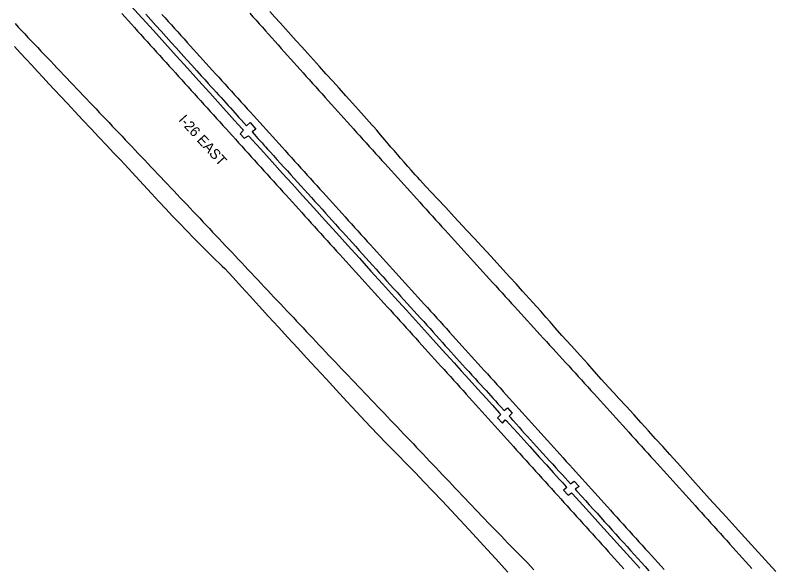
# Model space of a CAD drawing. Extents: x 1948091 to 1975253, y 787267 to 823306.
# Drawn here: x 1958564 to 1958967.8, y 810575.6 to 810868.4 of the extents above; entities that cross this region are included whole.
import ezdxf

# ---------------------------------------------------------------- set-up
doc = ezdxf.new("R2010")
doc.units = 0
for name, color, linetype in [('RD_EX_Pavement_Markings', 7, 'Continuous'), ('RD_EX_Road', 7, 'Continuous'), ('RD_TX_RoadID', 7, 'Continuous')]:
    doc.layers.add(name, color=color, linetype=linetype)

msp = doc.modelspace()

# ---------------------------------------------------------------- linework, layer by layer
at = {"layer": 'RD_EX_Pavement_Markings'}
for points in [[(1958620.62, 810869.28), (1958622.29, 810867.42), (1958623.97, 810865.57), (1958625.64, 810863.71), (1958627.31, 810861.85), (1958628.99, 810860), (1958630.66, 810858.14), (1958632.33, 810856.29), (1958634.01, 810854.43), (1958635.68, 810852.58), (1958637.35, 810850.72), (1958639.03, 810848.87), (1958640.7, 810847.01), (1958642.38, 810845.16), (1958644.06, 810843.31), (1958645.73, 810841.46), (1958647.41, 810839.6), (1958649.09, 810837.75), (1958650.76, 810835.9), (1958652.44, 810834.04), (1958654.12, 810832.19), (1958655.79, 810830.34), (1958657.47, 810828.48), (1958659.15, 810826.63), (1958660.82, 810824.78), (1958662.5, 810822.92), (1958664.18, 810821.07), (1958665.85, 810819.22), (1958667.53, 810817.36), (1958669.21, 810815.51), (1958670.88, 810813.66), (1958672.56, 810811.8), (1958674.24, 810809.95), (1958675.91, 810808.1), (1958677.59, 810806.25), (1958679.27, 810804.39), (1958680.94, 810802.54), (1958682.62, 810800.69), (1958684.3, 810798.83), (1958685.97, 810796.98), (1958687.65, 810795.13), (1958689.33, 810793.27), (1958691.01, 810791.42), (1958692.68, 810789.57), (1958694.36, 810787.72), (1958696.04, 810785.86), (1958697.71, 810784.01), (1958699.39, 810782.16), (1958701.07, 810780.3), (1958702.75, 810778.45), (1958704.42, 810776.6), (1958706.1, 810774.74), (1958707.78, 810772.89), (1958709.46, 810771.04), (1958711.13, 810769.19), (1958712.81, 810767.33), (1958714.49, 810765.48), (1958716.17, 810763.63), (1958717.84, 810761.77), (1958719.52, 810759.92), (1958721.2, 810758.07), (1958722.88, 810756.21), (1958724.55, 810754.36), (1958726.23, 810752.51), (1958727.91, 810750.66), (1958729.59, 810748.8), (1958731.26, 810746.95), (1958732.94, 810745.1), (1958734.62, 810743.24), (1958736.3, 810741.39), (1958737.98, 810739.54), (1958739.66, 810737.69), (1958741.34, 810735.84), (1958743.01, 810733.99), (1958744.69, 810732.13), (1958746.37, 810730.28), (1958748.05, 810728.43), (1958749.73, 810726.58), (1958751.41, 810724.73), (1958753.09, 810722.87), (1958754.77, 810721.02), (1958756.45, 810719.17), (1958758.13, 810717.32), (1958759.81, 810715.47), (1958761.49, 810713.62), (1958763.16, 810711.76), (1958764.84, 810709.91), (1958766.52, 810708.06), (1958768.2, 810706.21), (1958769.88, 810704.36), (1958771.56, 810702.5), (1958773.24, 810700.65), (1958774.92, 810698.8), (1958776.6, 810696.95), (1958778.28, 810695.1), (1958779.95, 810693.24), (1958781.63, 810691.39), (1958783.3, 810689.53), (1958784.98, 810687.68), (1958786.65, 810685.82), (1958788.33, 810683.97), (1958790.01, 810682.11), (1958791.68, 810680.26), (1958793.36, 810678.4), (1958795.03, 810676.55), (1958796.71, 810674.69), (1958798.38, 810672.84), (1958800.06, 810670.98), (1958801.74, 810669.13), (1958803.41, 810667.27), (1958805.09, 810665.42), (1958806.76, 810663.56), (1958808.44, 810661.7), (1958810.11, 810659.85), (1958811.79, 810657.99), (1958813.47, 810656.14), (1958815.14, 810654.28), (1958816.82, 810652.43), (1958818.49, 810650.57), (1958820.17, 810648.72), (1958821.84, 810646.86), (1958823.52, 810645.01), (1958825.2, 810643.15), (1958826.87, 810641.3), (1958828.55, 810639.44), (1958830.22, 810637.59), (1958831.9, 810635.73), (1958833.57, 810633.87), (1958835.25, 810632.02), (1958836.92, 810630.16), (1958838.6, 810628.31), (1958840.27, 810626.45), (1958841.95, 810624.59), (1958843.62, 810622.74), (1958845.3, 810620.88), (1958846.97, 810619.03), (1958848.65, 810617.17), (1958850.32, 810615.31), (1958852, 810613.46), (1958853.67, 810611.6), (1958855.35, 810609.75), (1958857.02, 810607.89), (1958858.7, 810606.03), (1958860.37, 810604.18), (1958862.05, 810602.32), (1958863.72, 810600.47), (1958865.4, 810598.61), (1958867.07, 810596.76), (1958868.75, 810594.9), (1958870.42, 810593.04), (1958872.1, 810591.19), (1958873.77, 810589.33), (1958875.45, 810587.48), (1958877.13, 810585.63), (1958878.81, 810583.77), (1958880.48, 810581.92), (1958882.16, 810580.07), (1958883.84, 810578.21), (1958885.52, 810576.36), (1958887.19, 810574.51)], [(1958641.89, 810868.81), (1958643.57, 810866.95), (1958645.24, 810865.1), (1958646.91, 810863.24), (1958648.59, 810861.39), (1958650.26, 810859.53), (1958651.94, 810857.67), (1958653.61, 810855.82), (1958655.28, 810853.96), (1958656.96, 810852.11), (1958658.64, 810850.26), (1958660.32, 810848.41), (1958662, 810846.56), (1958663.68, 810844.71), (1958665.36, 810842.86), (1958667.04, 810841.01), (1958668.72, 810839.16), (1958670.4, 810837.31), (1958672.08, 810835.46), (1958673.76, 810833.61), (1958675.44, 810831.76), (1958677.11, 810829.91), (1958678.79, 810828.06), (1958680.47, 810826.21), (1958682.15, 810824.36), (1958683.83, 810822.51), (1958685.51, 810820.66), (1958687.19, 810818.81), (1958688.87, 810816.96), (1958690.55, 810815.1), (1958692.23, 810813.25), (1958693.9, 810811.39), (1958695.58, 810809.54), (1958697.25, 810807.69), (1958698.93, 810805.83), (1958700.6, 810803.98), (1958702.28, 810802.12), (1958703.96, 810800.27), (1958705.63, 810798.41), (1958707.31, 810796.56), (1958708.98, 810794.71), (1958710.66, 810792.85), (1958712.33, 810791), (1958714.01, 810789.14), (1958715.69, 810787.29), (1958717.36, 810785.43), (1958719.04, 810783.58), (1958720.71, 810781.73), (1958722.39, 810779.87), (1958724.06, 810778.02), (1958725.74, 810776.16), (1958727.42, 810774.31), (1958729.1, 810772.46), (1958730.78, 810770.61), (1958732.45, 810768.75), (1958734.13, 810766.9), (1958735.81, 810765.05), (1958737.49, 810763.19), (1958739.17, 810761.34), (1958740.84, 810759.49), (1958742.52, 810757.64), (1958744.2, 810755.78), (1958745.88, 810753.93), (1958747.56, 810752.08), (1958749.23, 810750.23), (1958750.91, 810748.37), (1958752.59, 810746.52), (1958754.27, 810744.67), (1958755.95, 810742.82), (1958757.62, 810740.96), (1958759.3, 810739.11), (1958760.98, 810737.26), (1958762.66, 810735.4), (1958764.34, 810733.55), (1958766.02, 810731.7), (1958767.69, 810729.85), (1958769.37, 810728), (1958771.05, 810726.14), (1958772.73, 810724.29), (1958774.41, 810722.44), (1958776.09, 810720.59), (1958777.77, 810718.74), (1958779.45, 810716.88), (1958781.13, 810715.03), (1958782.81, 810713.18), (1958784.49, 810711.33), (1958786.16, 810709.48), (1958787.84, 810707.62), (1958789.52, 810705.77), (1958791.2, 810703.92), (1958792.88, 810702.07), (1958794.56, 810700.22), (1958796.24, 810698.36), (1958797.92, 810696.51), (1958799.59, 810694.66), (1958801.27, 810692.8), (1958802.94, 810690.95), (1958804.62, 810689.09), (1958806.3, 810687.24), (1958807.97, 810685.38), (1958809.65, 810683.53), (1958811.33, 810681.67), (1958813, 810679.82), (1958814.68, 810677.96), (1958816.35, 810676.11), (1958818.03, 810674.25), (1958819.71, 810672.4), (1958821.38, 810670.54), (1958823.06, 810668.69), (1958824.73, 810666.83), (1958826.41, 810664.98), (1958828.09, 810663.12), (1958829.76, 810661.27), (1958831.44, 810659.41), (1958833.11, 810657.56), (1958834.79, 810655.7), (1958836.47, 810653.85), (1958838.14, 810651.99), (1958839.82, 810650.14), (1958841.5, 810648.29), (1958843.17, 810646.43), (1958844.85, 810644.58), (1958846.52, 810642.72), (1958848.2, 810640.87), (1958849.88, 810639.01), (1958851.55, 810637.16), (1958853.23, 810635.3), (1958854.9, 810633.45), (1958856.58, 810631.59), (1958858.26, 810629.74), (1958859.93, 810627.88), (1958861.61, 810626.03), (1958863.28, 810624.17), (1958864.96, 810622.32), (1958866.64, 810620.46), (1958868.31, 810618.61), (1958869.99, 810616.75), (1958871.67, 810614.9), (1958873.34, 810613.04), (1958875.02, 810611.19), (1958876.69, 810609.33), (1958878.37, 810607.48), (1958880.05, 810605.62), (1958881.72, 810603.77), (1958883.4, 810601.91), (1958885.07, 810600.06), (1958886.75, 810598.21), (1958888.43, 810596.35), (1958890.11, 810594.5), (1958891.79, 810592.65), (1958893.46, 810590.79), (1958895.14, 810588.94), (1958896.82, 810587.09), (1958898.5, 810585.23), (1958900.18, 810583.38), (1958901.85, 810581.53), (1958903.53, 810579.67), (1958905.21, 810577.82), (1958906.89, 810575.97), (1958908.56, 810574.11)], [(1958688.55, 810869.48), (1958690.21, 810867.62), (1958691.88, 810865.75), (1958693.54, 810863.89), (1958695.21, 810862.02), (1958696.87, 810860.16), (1958698.54, 810858.3), (1958700.2, 810856.43), (1958701.87, 810854.57), (1958703.53, 810852.71), (1958705.2, 810850.84), (1958706.86, 810848.98), (1958708.53, 810847.12), (1958710.2, 810845.26), (1958711.87, 810843.4), (1958713.53, 810841.54), (1958715.2, 810839.67), (1958716.87, 810837.81), (1958718.54, 810835.95), (1958720.21, 810834.09), (1958721.88, 810832.23), (1958723.55, 810830.37), (1958725.21, 810828.51), (1958726.88, 810826.65), (1958728.55, 810824.79), (1958730.22, 810822.93), (1958731.89, 810821.07), (1958733.57, 810819.21), (1958735.24, 810817.36), (1958736.91, 810815.5), (1958738.58, 810813.64), (1958740.25, 810811.78), (1958741.92, 810809.92), (1958743.59, 810808.06), (1958745.26, 810806.2), (1958746.94, 810804.35), (1958748.62, 810802.5), (1958750.29, 810800.64), (1958751.97, 810798.79), (1958753.65, 810796.94), (1958755.33, 810795.09), (1958757.01, 810793.23), (1958758.68, 810791.38), (1958760.36, 810789.53), (1958762.04, 810787.68), (1958763.72, 810785.82), (1958765.4, 810783.97), (1958767.07, 810782.12), (1958768.75, 810780.26), (1958770.43, 810778.41), (1958772.1, 810776.56), (1958773.78, 810774.7), (1958775.46, 810772.85), (1958777.13, 810770.99), (1958778.81, 810769.14), (1958780.49, 810767.29), (1958782.16, 810765.43), (1958783.84, 810763.58), (1958785.52, 810761.73), (1958787.2, 810759.87), (1958788.87, 810758.02), (1958790.55, 810756.16), (1958792.23, 810754.31), (1958793.9, 810752.46), (1958795.58, 810750.6), (1958797.26, 810748.75), (1958798.93, 810746.89), (1958800.61, 810745.04), (1958802.29, 810743.19), (1958803.96, 810741.33), (1958805.64, 810739.48), (1958807.32, 810737.62), (1958808.99, 810735.77), (1958810.67, 810733.92), (1958812.35, 810732.06), (1958814.03, 810730.22), (1958815.72, 810728.37), (1958817.41, 810726.52), (1958819.09, 810724.68), (1958820.78, 810722.83), (1958822.46, 810720.99), (1958824.15, 810719.14), (1958825.83, 810717.3), (1958827.52, 810715.45), (1958829.21, 810713.6), (1958830.89, 810711.76), (1958832.58, 810709.91), (1958834.26, 810708.07), (1958835.95, 810706.22), (1958837.63, 810704.37), (1958839.32, 810702.53), (1958841, 810700.68), (1958842.69, 810698.83), (1958844.37, 810696.99), (1958846.06, 810695.14), (1958847.74, 810693.29), (1958849.43, 810691.45), (1958851.11, 810689.6), (1958852.8, 810687.75), (1958854.48, 810685.91), (1958856.17, 810684.06), (1958857.85, 810682.21), (1958859.54, 810680.36), (1958861.22, 810678.52), (1958862.91, 810676.67), (1958864.59, 810674.82), (1958866.27, 810672.97), (1958867.96, 810671.13), (1958869.64, 810669.28), (1958871.33, 810667.43), (1958873.01, 810665.58), (1958874.7, 810663.74), (1958876.38, 810661.89), (1958878.05, 810660.03), (1958879.73, 810658.18), (1958881.4, 810656.32), (1958883.08, 810654.46), (1958884.75, 810652.61), (1958886.43, 810650.75), (1958888.1, 810648.9), (1958889.78, 810647.04), (1958891.45, 810645.18), (1958893.13, 810643.33), (1958894.8, 810641.47), (1958896.48, 810639.62), (1958898.16, 810637.76), (1958899.84, 810635.91), (1958901.52, 810634.06), (1958903.2, 810632.21), (1958904.87, 810630.36), (1958906.55, 810628.5), (1958908.23, 810626.65), (1958909.91, 810624.8), (1958911.59, 810622.95), (1958913.27, 810621.1), (1958914.95, 810619.24), (1958916.63, 810617.39), (1958918.3, 810615.53), (1958919.97, 810613.67), (1958921.65, 810611.82), (1958923.32, 810609.96), (1958924.99, 810608.1), (1958926.67, 810606.24), (1958928.34, 810604.39), (1958930.01, 810602.53), (1958931.69, 810600.67), (1958933.36, 810598.81), (1958935.03, 810596.96), (1958936.71, 810595.1), (1958938.38, 810593.24), (1958940.05, 810591.38), (1958941.72, 810589.52), (1958943.39, 810587.67), (1958945.07, 810585.81), (1958946.74, 810583.95), (1958948.41, 810582.09), (1958950.08, 810580.23), (1958951.75, 810578.37), (1958953.43, 810576.52), (1958955.1, 810574.66)], [(1958563.9, 810863.94), (1958565.62, 810862.12), (1958567.34, 810860.31), (1958569.05, 810858.49), (1958570.77, 810856.68), (1958572.49, 810854.86), (1958574.2, 810853.05), (1958575.92, 810851.23), (1958577.64, 810849.42), (1958579.36, 810847.61), (1958581.09, 810845.8), (1958582.81, 810843.99), (1958584.53, 810842.18), (1958586.25, 810840.37), (1958587.97, 810838.56), (1958589.69, 810836.75), (1958591.42, 810834.93), (1958593.14, 810833.12), (1958594.86, 810831.31), (1958596.58, 810829.5), (1958598.3, 810827.69), (1958600.03, 810825.88), (1958601.75, 810824.07), (1958603.47, 810822.26), (1958605.19, 810820.45), (1958606.91, 810818.64), (1958608.64, 810816.83), (1958610.36, 810815.02), (1958612.08, 810813.21), (1958613.8, 810811.4), (1958615.52, 810809.58), (1958617.24, 810807.77), (1958618.96, 810805.96), (1958620.68, 810804.14), (1958622.4, 810802.33), (1958624.12, 810800.52), (1958625.84, 810798.7), (1958627.56, 810796.89), (1958629.28, 810795.08), (1958631, 810793.26), (1958632.72, 810791.45), (1958634.44, 810789.64), (1958636.16, 810787.82), (1958637.88, 810786.01), (1958639.6, 810784.2), (1958641.31, 810782.38), (1958643.03, 810780.57), (1958644.75, 810778.76), (1958646.47, 810776.94), (1958648.19, 810775.13), (1958649.91, 810773.31), (1958651.63, 810771.5), (1958653.35, 810769.69), (1958655.07, 810767.87), (1958656.79, 810766.06), (1958658.51, 810764.24), (1958660.22, 810762.42), (1958661.94, 810760.61), (1958663.65, 810758.79), (1958665.37, 810756.97), (1958667.08, 810755.15), (1958668.8, 810753.33), (1958670.51, 810751.51), (1958672.23, 810749.7), (1958673.94, 810747.88), (1958675.66, 810746.06), (1958677.37, 810744.24), (1958679.09, 810742.42), (1958680.8, 810740.61), (1958682.52, 810738.79), (1958684.23, 810736.97), (1958685.95, 810735.15), (1958687.66, 810733.33), (1958689.38, 810731.51), (1958691.09, 810729.7), (1958692.81, 810727.88), (1958694.52, 810726.06), (1958696.24, 810724.24), (1958697.95, 810722.42), (1958699.67, 810720.6), (1958701.38, 810718.79), (1958703.1, 810716.97), (1958704.81, 810715.15), (1958706.53, 810713.33), (1958708.24, 810711.51), (1958709.95, 810709.69), (1958711.67, 810707.87), (1958713.38, 810706.05), (1958715.1, 810704.23), (1958716.81, 810702.41), (1958718.52, 810700.59), (1958720.24, 810698.78), (1958721.95, 810696.96), (1958723.67, 810695.14), (1958725.38, 810693.32), (1958727.1, 810691.5), (1958728.81, 810689.68), (1958730.52, 810687.86), (1958732.24, 810686.04), (1958733.95, 810684.22), (1958735.68, 810682.41), (1958737.4, 810680.6), (1958739.13, 810678.79), (1958740.85, 810676.99), (1958742.58, 810675.18), (1958744.31, 810673.37), (1958746.03, 810671.56), (1958747.76, 810669.75), (1958749.48, 810667.94), (1958751.21, 810666.14), (1958752.94, 810664.33), (1958754.66, 810662.52), (1958756.39, 810660.71), (1958758.12, 810658.9), (1958759.84, 810657.09), (1958761.57, 810655.29), (1958763.29, 810653.48), (1958765.02, 810651.67), (1958766.75, 810649.86), (1958768.47, 810648.05), (1958770.19, 810646.24), (1958771.92, 810644.43), (1958773.64, 810642.62), (1958775.36, 810640.8), (1958777.08, 810638.99), (1958778.81, 810637.18), (1958780.53, 810635.37), (1958782.25, 810633.56), (1958783.97, 810631.74), (1958785.69, 810629.93), (1958787.42, 810628.12), (1958789.14, 810626.31), (1958790.86, 810624.5), (1958792.58, 810622.68), (1958794.31, 810620.87), (1958796.03, 810619.06), (1958797.75, 810617.25), (1958799.47, 810615.43), (1958801.19, 810613.62), (1958802.92, 810611.81), (1958804.64, 810610), (1958806.36, 810608.19), (1958808.08, 810606.37), (1958809.81, 810604.56), (1958811.53, 810602.75), (1958813.25, 810600.94), (1958814.99, 810599.14), (1958816.73, 810597.34), (1958818.47, 810595.55), (1958820.21, 810593.76), (1958821.95, 810591.96), (1958823.69, 810590.17), (1958825.43, 810588.37), (1958827.17, 810586.58), (1958828.91, 810584.78), (1958830.66, 810582.99), (1958832.41, 810581.21), (1958834.16, 810579.42), (1958835.91, 810577.64), (1958837.66, 810575.85), (1958839.41, 810574.07)]]:
    msp.add_lwpolyline(points, dxfattribs=at)
at = {"layer": 'RD_EX_Road'}
for points in [[(1958625.45, 810873.45), (1958631.43, 810866.84), (1958637.35, 810860.3), (1958643.35, 810853.66), (1958649.42, 810846.93), (1958655.42, 810840.28), (1958661.35, 810833.74), (1958667.26, 810827.21), (1958673.02, 810820.85), (1958677.66, 810815.71), (1958680.49, 810812.55), (1958682.43, 810810.39), (1958684.54, 810808.07), (1958685.2, 810807.33), (1958683.4, 810805.47), (1958685.57, 810803.13), (1958687.79, 810804.44), (1958688.3, 810803.87), (1958689.84, 810802.2), (1958694.33, 810797.28), (1958700.36, 810790.63), (1958705.97, 810784.43), (1958711.01, 810778.87), (1958716.49, 810772.8), (1958722.5, 810766.12), (1958728.53, 810759.45), (1958734.5, 810752.86), (1958740.55, 810746.18), (1958746.69, 810739.39), (1958752.86, 810732.58), (1958759.06, 810725.75), (1958765.34, 810718.83), (1958771.71, 810711.81), (1958778.07, 810704.78), (1958784.4, 810697.77), (1958790.64, 810690.86), (1958797.01, 810683.81), (1958800.76, 810679.67), (1958804.96, 810675.03), (1958809.61, 810669.89), (1958813.98, 810665.06), (1958817.33, 810661.35), (1958821, 810657.28), (1958821.73, 810656.46), (1958820.11, 810654.68), (1958822.66, 810651.86), (1958824.2, 810653.7), (1958824.78, 810653.05), (1958826.17, 810651.55), (1958830.77, 810646.52), (1958837.23, 810639.4), (1958842.42, 810633.67), (1958846.05, 810629.66), (1958849.64, 810625.69), (1958853.04, 810621.92), (1958854.66, 810620.13), (1958856.54, 810618.04), (1958856.85, 810617.7)], [(1958633.28, 810868.94), (1958636.01, 810865.92), (1958638.73, 810862.9), (1958641.42, 810859.91), (1958644.09, 810856.95), (1958646.73, 810854.02), (1958649.39, 810851.07), (1958652.12, 810848.05), (1958654.9, 810844.98), (1958657.75, 810841.85), (1958660.45, 810838.88), (1958662.8, 810836.29), (1958664.8, 810834.09), (1958666.45, 810832.26), (1958667.9, 810830.65), (1958669.3, 810829.1), (1958670.66, 810827.6), (1958671.97, 810826.17), (1958673.25, 810824.77), (1958674.53, 810823.36), (1958675.79, 810821.96), (1958677.05, 810820.56), (1958678.27, 810819.18), (1958679.45, 810817.87), (1958680.57, 810816.62), (1958681.65, 810815.42), (1958682.76, 810814.19), (1958683.98, 810812.84), (1958685.31, 810811.37), (1958686.75, 810809.77), (1958688.67, 810811.4), (1958691.72, 810808), (1958689.71, 810806.51), (1958690.9, 810805.2), (1958691.95, 810804.02), (1958692.87, 810802.99), (1958693.67, 810802.11), (1958694.37, 810801.32), (1958695.03, 810800.59), (1958695.64, 810799.92), (1958696.2, 810799.3), (1958696.91, 810798.53), (1958697.96, 810797.37), (1958699.35, 810795.84), (1958701.08, 810793.92), (1958702.97, 810791.83), (1958704.84, 810789.77), (1958706.68, 810787.74), (1958708.49, 810785.74), (1958710.3, 810783.75), (1958712.1, 810781.76), (1958713.91, 810779.77), (1958715.71, 810777.78), (1958717.53, 810775.78), (1958719.37, 810773.74), (1958721.24, 810771.68), (1958723.13, 810769.59), (1958725.02, 810767.51), (1958726.88, 810765.45), (1958728.71, 810763.42), (1958730.51, 810761.42), (1958732.3, 810759.43), (1958734.09, 810757.45), (1958735.88, 810755.46), (1958737.67, 810753.48), (1958739.47, 810751.5), (1958741.25, 810749.52), (1958743.03, 810747.54), (1958744.79, 810745.56), (1958746.56, 810743.59), (1958748.34, 810741.61), (1958750.13, 810739.63), (1958751.92, 810737.65), (1958753.73, 810735.65), (1958755.57, 810733.62), (1958757.43, 810731.57), (1958759.32, 810729.48), (1958761.2, 810727.4), (1958763.06, 810725.34), (1958764.9, 810723.32), (1958766.71, 810721.33), (1958768.5, 810719.35), (1958770.31, 810717.37), (1958772.11, 810715.39), (1958773.92, 810713.41), (1958775.71, 810711.44), (1958777.47, 810709.51), (1958779.2, 810707.61), (1958780.89, 810705.74), (1958782.56, 810703.88), (1958784.23, 810702.03), (1958785.9, 810700.17), (1958787.56, 810698.31), (1958789.2, 810696.48), (1958790.79, 810694.71), (1958792.33, 810692.99), (1958793.83, 810691.33), (1958795.31, 810689.69), (1958796.82, 810688.02), (1958798.36, 810686.31), (1958799.91, 810684.58), (1958801.5, 810682.82), (1958803.12, 810681.03), (1958804.77, 810679.21), (1958806.45, 810677.35), (1958808.11, 810675.53), (1958809.69, 810673.8), (1958811.19, 810672.15), (1958812.61, 810670.6), (1958813.96, 810669.12), (1958815.26, 810667.7), (1958816.51, 810666.34), (1958817.71, 810665.03), (1958818.94, 810663.68), (1958820.3, 810662.19), (1958821.79, 810660.55), (1958823.4, 810658.76), (1958823.52, 810658.62), (1958825.32, 810659.94), (1958827.78, 810657.15), (1958826.26, 810655.54), (1958826.69, 810655.05), (1958828.08, 810653.49), (1958828.34, 810653.21), (1958829.93, 810651.43), (1958831.48, 810649.71), (1958832.98, 810648.05), (1958834.46, 810646.4), (1958835.98, 810644.73), (1958837.52, 810643.02), (1958839.09, 810641.29), (1958840.7, 810639.52), (1958842.36, 810637.69), (1958844.06, 810635.81), (1958845.82, 810633.88), (1958847.6, 810631.93), (1958849.35, 810630.01), (1958851.09, 810628.11), (1958852.81, 810626.24), (1958854.47, 810624.44), (1958856.02, 810622.76), (1958857.46, 810621.19), (1958858.79, 810619.73), (1958860.7, 810621.14), (1958863.35, 810618.24), (1958861.35, 810616.8), (1958862.03, 810616.02), (1958863.38, 810614.52), (1958863.67, 810614.2), (1958864.95, 810612.78), (1958866.73, 810610.8), (1958868.73, 810608.59), (1958870.82, 810606.28), (1958872.88, 810604), (1958874.92, 810601.74), (1958876.93, 810599.52), (1958878.93, 810597.32), (1958880.92, 810595.12), (1958882.91, 810592.91), (1958884.89, 810590.71), (1958886.86, 810588.52), (1958888.81, 810586.36), (1958890.73, 810584.23), (1958892.62, 810582.12), (1958894.52, 810580.02), (1958896.45, 810577.89), (1958898.41, 810575.73), (1958900.39, 810573.54)], [(1958967.8, 810573.06), (1958962.24, 810579.23), (1958956.75, 810585.3), (1958951.41, 810591.19), (1958946.28, 810596.84), (1958941.45, 810602.14), (1958937.01, 810606.99), (1958932.69, 810611.71), (1958928.21, 810616.65), (1958923.78, 810621.57), (1958919.61, 810626.26), (1958915.59, 810630.77), (1958911.62, 810635.16), (1958907.75, 810639.44), (1958904.01, 810643.6), (1958900.27, 810647.77), (1958896.41, 810652.04), (1958892.42, 810656.43), (1958888.29, 810660.94), (1958884.55, 810664.99), (1958881.76, 810668.02), (1958878.99, 810671.04), (1958875.33, 810675.08), (1958871.42, 810679.4), (1958867.92, 810683.27), (1958864.07, 810687.53), (1958859.11, 810693.04), (1958854.24, 810698.48), (1958850.68, 810702.55), (1958847.99, 810705.66), (1958845.76, 810708.2), (1958843.04, 810711.24), (1958838.88, 810715.86), (1958833.35, 810721.99), (1958830.08, 810725.59), (1958826.48, 810729.55), (1958822.88, 810733.5), (1958816.68, 810740.29), (1958811.74, 810745.67), (1958807.64, 810750.09), (1958803.79, 810754.19), (1958797.12, 810761.34), (1958792.53, 810766.28), (1958788, 810771.15), (1958781.89, 810777.75), (1958778.98, 810780.88), (1958777.71, 810782.3), (1958776.37, 810783.77), (1958774.19, 810786.2), (1958772.5, 810788.1), (1958770.5, 810790.4), (1958768.59, 810792.62), (1958767.07, 810794.37), (1958765.17, 810796.54), (1958763.5, 810798.44), (1958761.94, 810800.23), (1958760.18, 810802.28), (1958757.9, 810804.94), (1958757.2, 810805.85), (1958755.97, 810807.32), (1958754.21, 810809.32), (1958753.41, 810810.21), (1958751.91, 810811.87), (1958749.22, 810814.85), (1958746.26, 810818.13), (1958743.03, 810821.72), (1958739.53, 810825.61), (1958735.93, 810829.61), (1958732.41, 810833.53), (1958728.96, 810837.37), (1958725.59, 810841.13), (1958722.3, 810844.78), (1958719.14, 810848.29), (1958716.08, 810851.67), (1958713.14, 810854.91), (1958710.28, 810858.07), (1958707.44, 810861.2), (1958704.64, 810864.32), (1958701.86, 810867.41), (1958699.13, 810870.46)], [(1958563.52, 810851.78), (1958566.69, 810848.44), (1958569.78, 810845.13), (1958572.79, 810841.84), (1958575.77, 810838.57), (1958578.78, 810835.29), (1958581.82, 810832.02), (1958584.88, 810828.75), (1958588.13, 810825.29), (1958591.72, 810821.47), (1958595.64, 810817.28), (1958599.9, 810812.73), (1958604.24, 810808.1), (1958608.4, 810803.68), (1958612.38, 810799.45), (1958616.19, 810795.43), (1958619.98, 810791.41), (1958623.9, 810787.23), (1958627.96, 810782.87), (1958632.15, 810778.34), (1958636.31, 810773.84), (1958640.27, 810769.58), (1958644.03, 810765.57), (1958647.58, 810761.81), (1958651.15, 810758.06), (1958654.97, 810754.09), (1958659.04, 810749.92), (1958662.9, 810746), (1958663.36, 810745.53), (1958667.31, 810741.56), (1958670.25, 810738.64), (1958672.2, 810736.76), (1958673.15, 810735.92), (1958673.89, 810735.27), (1958675.22, 810733.93), (1958677.15, 810731.91), (1958679.66, 810729.2), (1958684.05, 810724.31), (1958688.66, 810719.22), (1958693.5, 810713.92), (1958698.55, 810708.4), (1958703.69, 810702.82), (1958708.77, 810697.3), (1958713.8, 810691.84), (1958718.76, 810686.44), (1958723.79, 810680.98), (1958729.01, 810675.32), (1958734.42, 810669.47), (1958740.01, 810663.43), (1958745.29, 810657.73), (1958749.77, 810652.92), (1958756.3, 810646), (1958761.26, 810640.9), (1958766.28, 810635.88), (1958772.47, 810629.6), (1958776.43, 810625.5), (1958780.96, 810620.75), (1958785.77, 810615.68), (1958790.58, 810610.58), (1958795.39, 810605.46), (1958800.2, 810600.33), (1958804.79, 810595.41), (1958808.94, 810590.94), (1958812.65, 810586.93), (1958819.02, 810579.98), (1958825.53, 810572.78)], [(1958856.85, 810617.7), (1958855.1, 810616.36), (1958857.62, 810613.55), (1958859.35, 810614.89), (1958859.87, 810614.31), (1958863.63, 810610.2), (1958868.92, 810604.36), (1958874.73, 810597.92), (1958880.07, 810592.02), (1958885.22, 810586.34), (1958890.45, 810580.55), (1958895.61, 810574.85)]]:
    msp.add_lwpolyline(points, dxfattribs=at)

# ---------------------------------------------------------------- texts
at = {"layer": 'RD_TX_RoadID'}
msp.add_text('I-26 EAST', height=5.4, rotation=312.2551, dxfattribs=at).set_placement((1958650.37, 810812.6))

doc.saveas('drawing.dxf')
